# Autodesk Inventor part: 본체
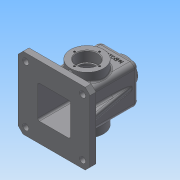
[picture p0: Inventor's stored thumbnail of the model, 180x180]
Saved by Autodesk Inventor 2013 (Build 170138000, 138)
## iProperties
Created: 2018-10
Part Number: 본체
Material: 일반
Document SubType Name: Modeling
Designer: Administrator
Density: 1 g/cm^3
Author: Administrator
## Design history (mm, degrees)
sketch "스케치1"
  geometry: L1 (-32.5, 32.5)-(32.5, 32.5); L2 (32.5, 32.5)-(32.5, -32.5); L3 (32.5, -32.5)-(-32.5, -32.5); L4 (-32.5, -32.5)-(-32.5, 32.5); L5 (-32.5, 32.5)-(32.5, -32.5); L6 (32.5, 32.5)-(-32.5, -32.5); 1 further point
  constraints: 12 end point, 2 midpoint, 2 parallel, 1 horizontal, 1 perpendicular
  dimensions: "d0" = 65 distance of L2.end L3.end; "d1" = 65 distance of L1.end L2.end
extrude "돌출1" new body sketch "스케치1" stored distance "d2" = 110; taper "d3" = 0 deg
sketch "스케치2"
  geometry: C1 r 27.5 at (32.5, -55); 1 further point
  constraints: 1 centre point, 1 coincident
  dimensions: "d4" = 55 diameter of C1
extrude "돌출2" join sketch "스케치2" distance "d5" = 15; taper "d6" = 0 deg
sketch "스케치3"
  geometry: C1 r 27.5 at (0, 0) reference; C2 r 17.5 at (0, 0)
  constraints: 1 centre point, 1 coincident
  dimensions: "d7" = 35 diameter of C2
extrude "돌출3" cut sketch "스케치3" distance "d8" = 17; taper "d9" = 0 deg
sketch "스케치4"
  geometry: C1 r 27.5 at (32.5, -55); 1 further point
  constraints: 1 centre point, 1 coincident
  dimensions: "d10" = 55 diameter of C1
extrude "돌출4" join sketch "스케치4" distance "d11" = 15; taper "d12" = 0 deg
sketch "스케치5"
  geometry: C1 r 27.5 at (0, 0) reference; C2 r 17.5 at (0, 0)
  constraints: 1 centre point, 1 coincident
  dimensions: "d13" = 35 diameter of C2
extrude "돌출5" cut sketch "스케치5" distance "d14" = 17; taper "d15" = 0 deg
feature "쉘1" dims "d16" = 5
hole "구멍1" diameter "d19" = 30; stored, may be unused: countersink angle "d23" = 90 deg, drill point angle "d25" = 118 deg; dims "d17" = 10, "d18" = 10, "d20" = 6, "d21" = 4, "d22" = 2, "d24" = 8
sketch "스케치6"
  geometry: L1 (32.5, 32.5)-(-32.5, 32.5) reference; L2 (-32.5, 32.5)-(-32.5, -32.5) reference; L3 (-32.5, -32.5)-(32.5, -32.5) reference; L4 (32.5, -32.5)-(32.5, 32.5) reference; L5 (-60, 60)-(60, 60); L6 (60, 60)-(60, -60); L7 (60, -60)-(-60, -60); L8 (-60, -60)-(-60, 60); L9 (-60, 60)-(60, -60); L10 (60, 60)-(-60, -60); 1 further point
  constraints: 12 end point, 2 midpoint, 2 parallel, 1 horizontal, 1 perpendicular
  dimensions: "d26" = 120 distance of L6.end L7.end; "d27" = 120 distance of L5.end L6.end
extrude "돌출6" join sketch "스케치6" distance "d28" = 10; taper "d29" = 0 deg
fillet "모깎기1" dims "d30" = 8
fillet "모깎기2" dims "d31" = 8
fillet "모깎기3" dims "d32" = 3
fillet "모깎기4" dims "d33" = 3
chamfer "모따기1" distance "d34" = 8; stored, may be unused: second distance "d35" = 2, angle "d36" = 45 deg
node "작업 평면1"
sketch "스케치7"
  geometry: C1 r 20 at (0, 0); 1 further point
  constraints: 1 centre point, 1 coincident
  dimensions: "d38" = 40 diameter of C1
extrude "돌출7" join sketch "스케치7" distance "d39" = 10; taper "d40" = 7 deg
hole "구멍2" diameter "d43" = 22.835; stored, may be unused: countersink angle "d47" = 90 deg, drill point angle "d49" = 118 deg; dims "d41" = 10, "d42" = 10, "d44" = 50, "d45" = 4, "d46" = 2, "d48" = 8
sketch "스케치8"
  geometry: C1 r 5 at (47.5, 47.5); 1 further point
  constraints: 1 centre point
  dimensions: "d50" = 10 diameter of C1; "d51" = 47.5 horizontal distance of C1.centre point (0, 0); "d52" = 47.5 horizontal distance of C1.centre point (0, 0)
extrude "돌출8" cut sketch "스케치8" stored distance "d53" = 10; taper "d54" = 0 deg
sketch "스케치9"
  geometry: L1 (42.5, -45)-(52.5, -45) reference; L2 (32.5, 47)-(32.5, -45) reference; L3 (52, -45)-(-52, -45) reference; L4 (48, -45)-(32.5, 42.905); L5 (60, -45)-(60, -55) reference; 1 further point
  constraints: 2 end point, 2 point on line
  dimensions: "d55" = 12 distance from line of L5 L4.start; "d56" = 10 deg angle of L5 L4
feature "리브1" sketch "스케치9" dims "d57" = 1, "d58" = 10, "d59" = 0, "d60" = 0, "d61" = 1, "d62" = 1
sketch "스케치11"
  geometry: L1 (27.5, 47.5)-(-27.5, 47.5) reference; L2 (12.49, 32.5)-(12.49, 32.5) reference; L3 (-12.49, 32.5)-(-12.49, 32.5) reference; L4 (-27.5, 32.5)-(-27.5, 47.5) reference; L5 (-55, -52)-(-55, 52) reference; L6 (-45, 52)-(-55, 52) reference; L7 (-45, -52)-(-45, 52) reference; L8 (-55, -52)-(-45, -52) reference; L9 (-45, 42.5)-(-27.5, 42.5); L10 (-45, 32.5)-(-12.49, 32.5) reference; L11 (47, 27.5)-(-55, 27.5) reference; 1 further point
  constraints: 2 end point, 2 horizontal alignment, 2 point on line, 1 parallel
  dimensions: "d65" = 15 distance between parallel lines of L11 L9
feature "리브2" sketch "스케치11" dims "d66" = 1, "d67" = 6, "d68" = 0, "d69" = 0, "d70" = 1, "d71" = 1
fillet "모깎기5" dims "d72" = 3
fillet "모깎기6" dims "d73" = 3
fillet "모깎기7" dims "d74" = 3
fillet "모깎기8" dims "d75" = 3
fillet "모깎기9" dims "d76" = 3
sketch "스케치12"
  geometry: L1 (0, 0)-(0, 21); C1 r 27.5 at (0, 0) reference; 1 further point
  constraints: 2 end point, 1 coincident, 1 vertical
  dimensions: "d77" = 21 distance of L1.start L1.end
hole "구멍3" sketch "스케치12" at (0, 21) diameter "d78" = 3.242; stored, may be unused: countersink angle "d82" = 90 deg, drill point angle "d84" = 118 deg; dims "d79" = 8, "d80" = 4, "d81" = 2, "d83" = 10
fillet "모깎기10" dims "d88" = 0.3
chamfer "모따기2" distance "d89" = 1; stored, may be unused: second distance "d90" = 2, angle "d91" = 45 deg
chamfer "모따기3" distance "d95" = 1; stored, may be unused: second distance "d96" = 2, angle "d97" = 45 deg
fillet "모깎기11" dims "d98" = 3
fillet "모깎기12" dims "d99" = 1
sketch "스케치14"
  geometry: L1 (-24.5, 27.5)-(24.5, 27.5) reference; L2 (27.5, 24.5)-(27.5, -24.5) reference; L3 (24.5, -27.5)-(-24.5, -27.5) reference; L4 (-27.5, -24.5)-(-27.5, 24.5) reference; A1 r 3 centre (24.5, 24.5) between (27.5, 24.5) and (24.5, 27.5) reference; A2 r 3 centre (24.5, -24.5) between (24.5, -27.5) and (27.5, -24.5) reference; A3 r 3 centre (-24.5, -24.5) between (-27.5, -24.5) and (-24.5, -27.5) reference; A4 r 3 centre (-24.5, 24.5) between (-24.5, 27.5) and (-27.5, 24.5) reference; 1 further point
extrude "돌출9" cut sketch "스케치14" distance "d100" = 88.5; taper "d101" = 0 deg
sketch "스케치15"
  geometry: L1 (-8, 0)-(-8, -91) reference; L2 (4.5, 18)-(44.5, 18) reference; 1 further point
  constraints: 1 other
  dimensions: "d102" = 32.5 distance from line of point (24.5, -8) L1; "d103" = 26 distance from line of L2 point (24.5, -8)
feature "엠보싱2" sketch "스케치15" dims "d104" = 0.5, "d105" = 0
node "솔리드1"
mirror "대칭1"
mirror "대칭2"
mirror "대칭3"
mirror "대칭4"
pattern_circular "원형 패턴1" dims angle "d86" = 360 deg
mirror "대칭5"
node "투영된 루프1"
node "투영된 루프2"
other parameters: "d37" = 65
